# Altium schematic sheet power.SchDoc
size A4
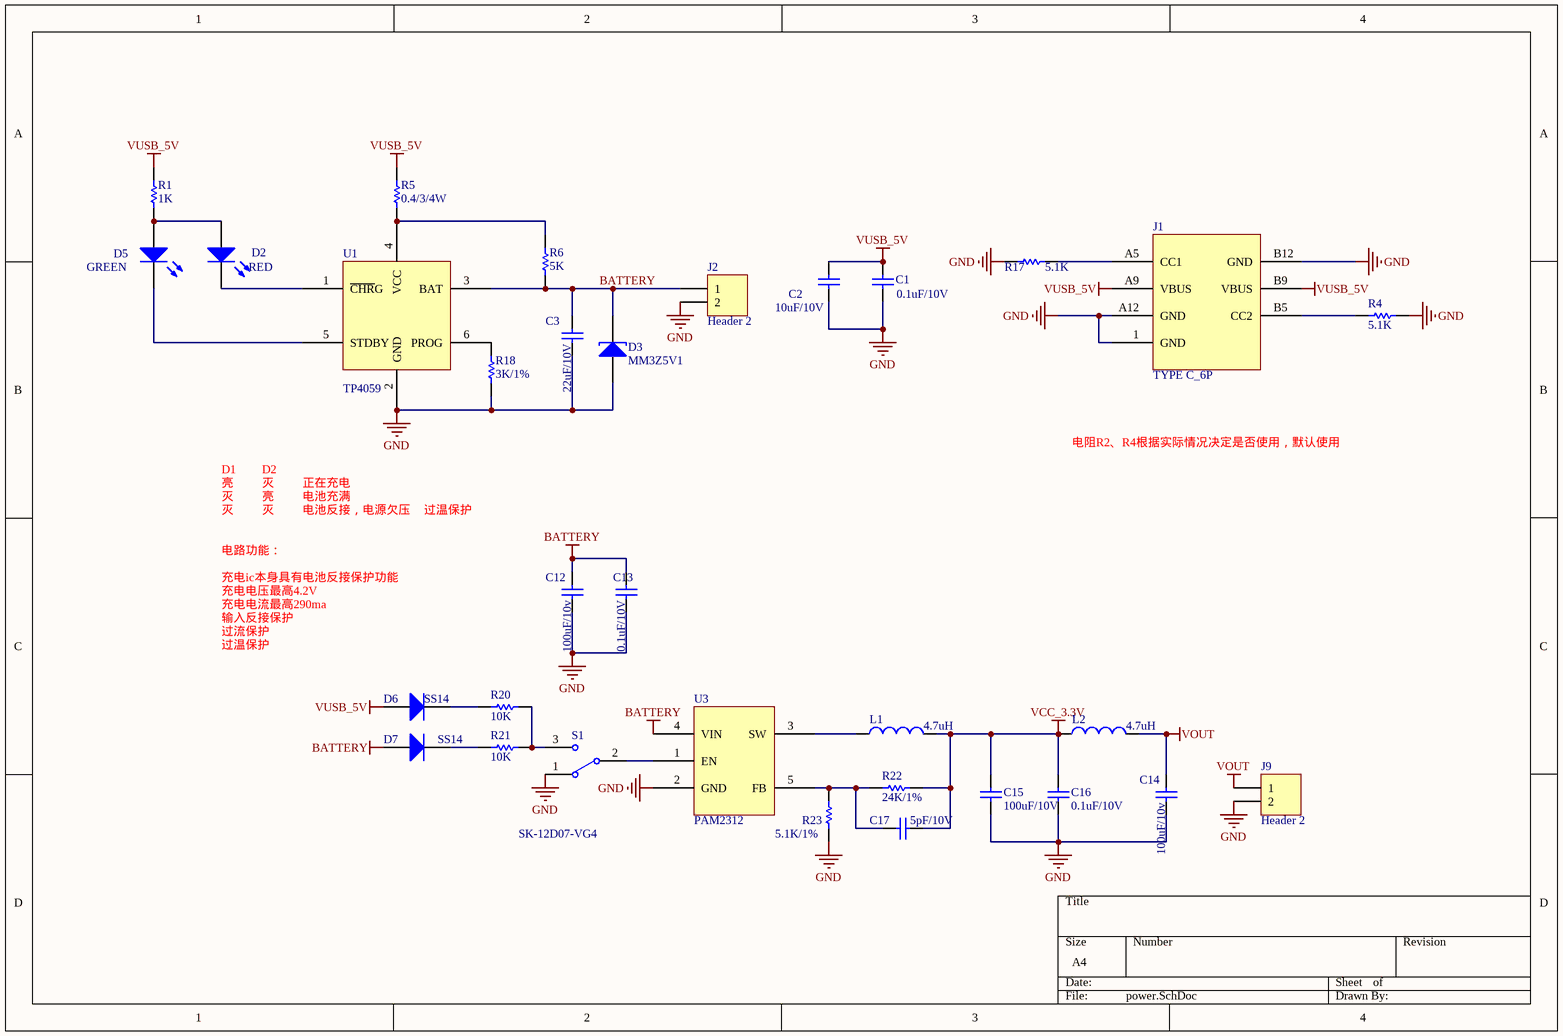
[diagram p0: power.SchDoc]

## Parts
C1  0.1uF/10V  [0402C]
C2  10uF/10V  [0603C]
C3  22uF/10V  [1206C]
C12  100uF/10v  [1206C]
C13  0.1uF/10V  [0402c]
C14  100uF/10v  [1206C]
C15  100uF/10V  [1206C]
C16  0.1uF/10V  [0402C]
C17  5pF/10V  [0402C]
D2  Publisher: RED  [0603LED]
D3  MM3Z5V1  [SOD323]
D5  Publisher: GREEN  [0603LED]
D6  SS14  [SMA]
D7  SS14  [SMA]
J1  TYPE C_6P  [TYPEC_6P]
J2  Header 2  [2X1.25MMZ]
J9  Header 2  [HDR1X2]
L1  4.7uH  [0805r]
L2  4.7uH  [0805r]
R1  1K  [0402R]
R4  5.1K  [0402R]
R5  0.4/3/4W  [2010R]
R6  5K  [0603R]
R17  5.1K  [0402R]
R18  3K/1%  [0402R]
R20  10K  [0402R]
R21  10K  [0402R]
R22  24K/1%  [0402R]
R23  5.1K/1%  [0402R]
S1  SK-12D07-VG4  [SK-12D07-VG4]
U1  TP4059  [sot-23-6]
U3  PAM2312  [SOT-23-5]

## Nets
BATTERY: C3.1 C12.1 C13.1 D3.2(K) D7.1(A) J2.1 R6.1 U1.3(BAT) U3.4(VIN)
GND: C1.1 C2.1 C3.2 C12.2 C13.2 C14.2 C15.1 C16.1 D3.1(A) J1.1(GND) J1.A12(GND) J1.B12(GND) J2.2 J9.2 R4.2 R17.2 R18.1 R23.1 S1.1 U1.2(GND) U3.2(GND)
VCC_3.3V: C15.2 C16.2 C17.2 L1.2 L2.1 R22.2
VOUT: C14.1 J9.1 L2.2
VUSB_5V: C1.2 C2.2 D6.1(A) J1.A9(VBUS) J1.B9(VBUS) R1.2 R5.1
NetC17_1: C17.1 R22.1 R23.2 U3.5(FB)
NetD2_1: D2.1(A) D5.1(A) R1.1
NetD2_2: D2.2(K) U1.1(~{CHR}G)
NetD5_2: D5.2(K) U1.5(STDBY)
NetD6_2: D6.2(K) R20.1
NetD7_2: D7.2(K) R21.1
NetJ1_A5: J1.A5(CC1) R17.1
NetJ1_B5: J1.B5(CC2) R4.1
NetL1_1: L1.1 U3.3(SW)
NetR5_2: R5.2 R6.2 U1.4(VCC)
NetR18_2: R18.2 U1.6(PROG)
NetR20_2: R20.2 R21.2 S1.3
NetS1_2: S1.2 U3.1(EN)

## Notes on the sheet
- 电阻R2、R4根据实际情况决定是否使用，默认使用
- D1
- 亮
- 灭
- D2
- 正在充电
- 电池充满
- 电池反接，电源欠压
- 过温保护
- 充电ic本身具有电池反接保护功能
- 电路功能：
- 输入反接保护
- 充电电流最高290ma
- 充电电压最高4.2V
- 过流保护

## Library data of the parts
C1-C3 C12-C17 = Cap: Capacitor; Value: 100pF
D2 D5 = LED0: Typical INFRARED GaAs LED
D3 = D Tunnel1: Tunnel Diode - RLC Model
D6 D7 = Diode: Default Diode
J2 J9 = Header 2: Header, 2-Pin
L1 L2 = Inductor: Code_IEC: 1005; Value: 10mH
R1 = Res Semi: Semiconductor Resistor
R4-R6 R17 R18 R20-R23 = Res Semi: Semiconductor Resistor; Value: 1K
S1 = SW-SPDT: SPDT Subminiature Toggle Switch, Right Angle Mounting, Vertical Actuation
